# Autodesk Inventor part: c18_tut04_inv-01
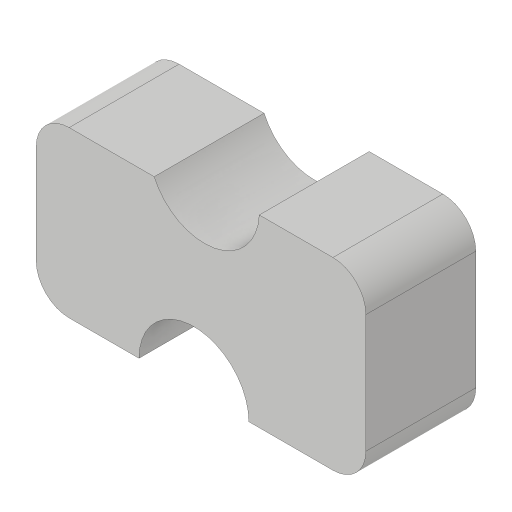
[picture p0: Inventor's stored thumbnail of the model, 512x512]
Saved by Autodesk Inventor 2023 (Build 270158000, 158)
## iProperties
Created: 2017-06
Part Number: c18_tut04_inv-01
Material: Generic
Document SubType Name: Modeling
Designer: CADCIM 00
Density: 1 g/cm^3
Appearance: Default
Author: CADCIM 00
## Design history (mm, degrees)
sketch "Sketch1"
  geometry: L1 (-60, 0)-(-60, 33.532); L2 (0, 30)-(0, 0); L3 (-60, 33.532)-(-40.6, 33.532); L4 (-21.474, 30)-(0, 30); L5 (0, 0)-(-18.704, 0); L6 (-38.704, 0)-(-60, 0); A1 r 10 centre (-30.614, 34.057) between (-40.6, 33.532) and (-21.474, 30); A2 r 10 centre (-28.704, 0) between (-18.704, 0) and (-38.704, 0)
  constraints: 12 end point, 5 parallel, 4 point on circle, 2 centre point, 2 horizontal, 2 perpendicular, 1 equal radius
  dimensions: "d0" = 60 distance between parallel lines of L1 L2 (= LEN); "d1" = 30 distance of L2.start L2.end (= WID); "d2" = 10 radius of A2 (= RAD)
extrude "Extrusion1" new body sketch "Sketch1" distance "d3" = 20 (= EXT); taper "d4" = 0 deg
fillet "Fillet1" dims "d5" = 6 (= FILLET)
body "Solid1"
other parameters: "LEN" = 60 [user parameter; used in 5 equation terms], "WID" = 30 (= 0.5 x LEN) [user parameter; used in 1 equation term], "RAD" = 10 (= 0.166667 x LEN) [user parameter; used in 1 equation term], "EXT" = 20 (= 0.333333 x LEN) [user parameter; used in 1 equation term], "FILLET" = 6 (= 0.1 x LEN) [user parameter; used in 1 equation term]
